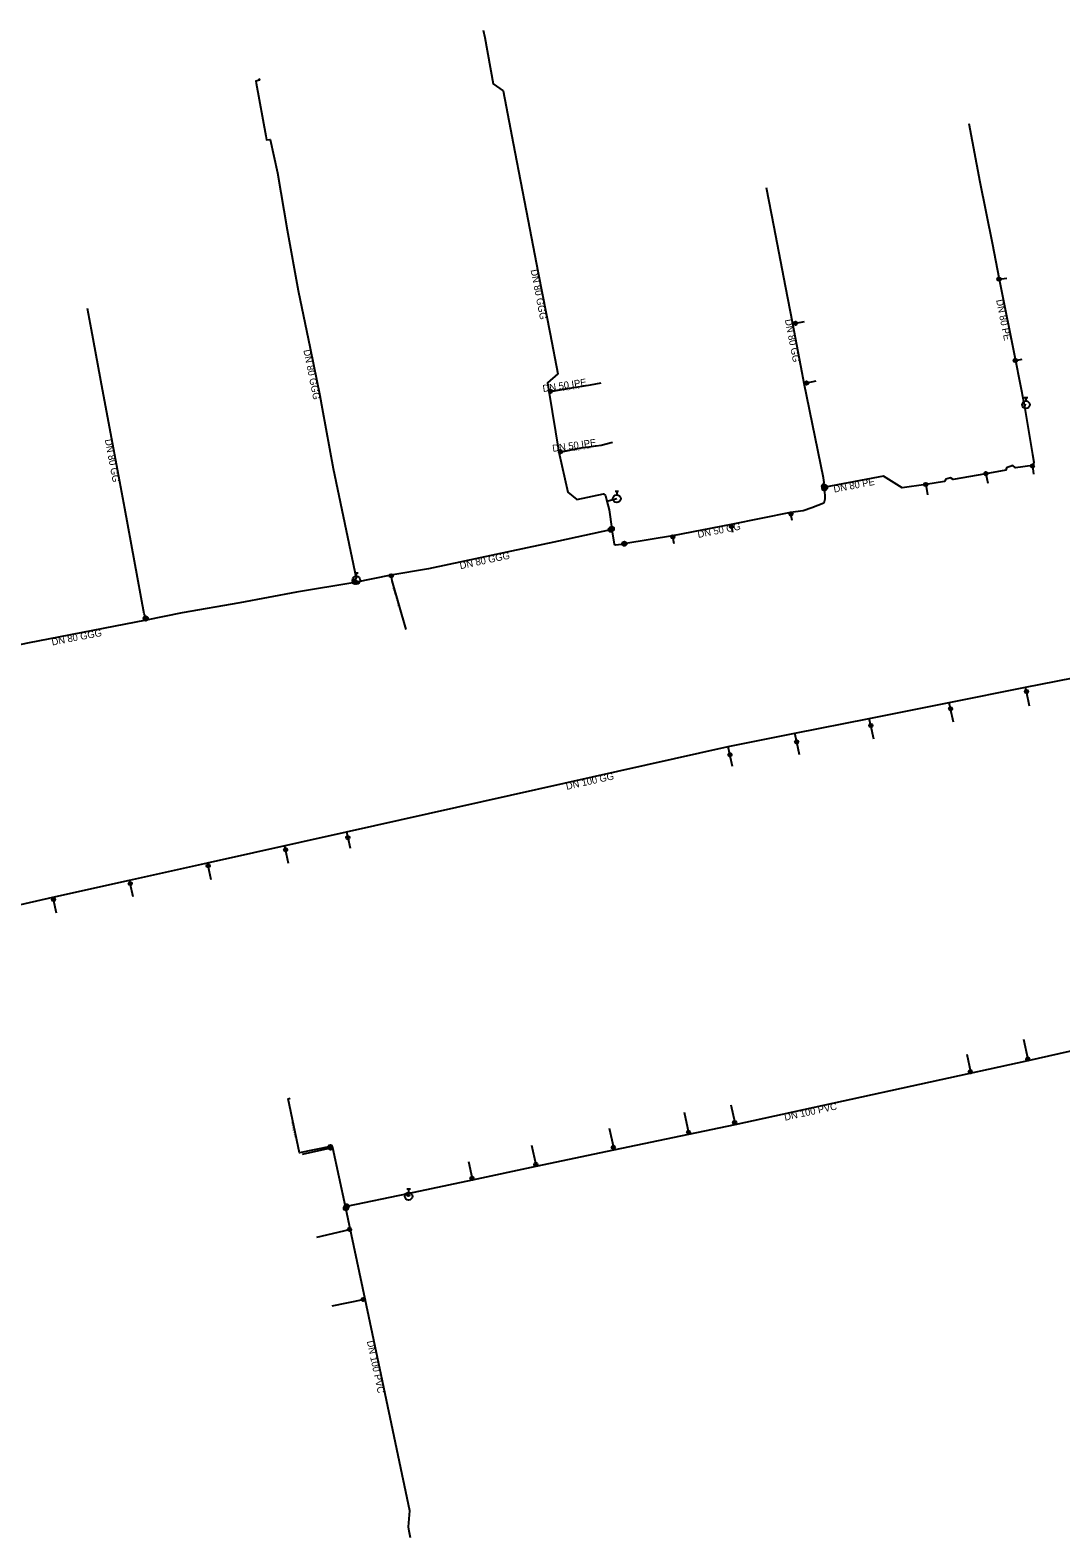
# Model space of a CAD drawing. Extents: x -452548 to -451108, y -1100145 to -1099658.
# Drawn here: x -452307.3 to -452071.3, y -1100124.5 to -1099779.2 of the extents above; entities that cross this region are included whole.
import ezdxf

# ---------------------------------------------------------------- set-up
doc = ezdxf.new("R2010")
doc.units = 0
for name, color, linetype in [('_hydrantova_odbocka_', 7, 'Continuous'), ('_pripojka_prevzato_z_dokumentace_', 7, 'Continuous'), ('_pripojka_priblizne_', 7, 'Continuous'), ('_voda_smvak_prevzato_z_dokumentace_', 7, 'Continuous'), ('_vodovodni_chranicka_', 7, 'Continuous'), ('Default', 7, 'Continuous'), ('MoLevel 27', 7, 'Continuous'), ('MoLevel 28', 7, 'Continuous'), ('MoLevel 32', 7, 'Continuous'), ('MoLevel 46', 7, 'Continuous'), ('MoLevel 53', 7, 'Continuous'), ('MoLevel 55', 7, 'Continuous'), ('MoLevel 60', 7, 'Continuous')]:
    doc.layers.add(name, color=color, linetype=linetype)

# ---------------------------------------------------------------- blocks, each defined once
blk = doc.blocks.new('_uzaver_')
at = {"layer": 'Default'}
for p, q in [((-0.000035, -0.000035), (0.000035, 0.000035)), ((0.000035, -0.000035), (-0.000035, 0.000035))]:
    blk.add_line(p, q, dxfattribs=at)
for radius in [0.00005, 0.0000025]:
    blk.add_circle((0, 0), radius, dxfattribs=at)
blk = doc.blocks.new('_uzaver_pripojka_')
at = {"layer": 'Default'}
for p, q in [((-0.000035, -0.000035), (0.000035, 0.000035)), ((0.000035, -0.000035), (-0.000035, 0.000035))]:
    blk.add_line(p, q, dxfattribs=at)
for radius in [0.00005, 0.0000025]:
    blk.add_circle((0, 0), radius, dxfattribs=at)
blk = doc.blocks.new('_hydrant_voda_')
at = {"layer": 'Default'}
for p, q in [((-0.000023, 0.000095), (0.000023, 0.000095)), ((0, 0.000095), (0, 0.00005))]:
    blk.add_line(p, q, dxfattribs=at)
blk.add_circle((0, 0), 0.00005, dxfattribs=at)

msp = doc.modelspace()

# ---------------------------------------------------------------- linework, layer by layer
at = {"layer": '_hydrantova_odbocka_'}
for p, q in [((-452079.72, -1099864.93), (-452079.34, -1099864.99)), ((-452175.26, -1099887.05), (-452173.01, -1099886.49)), ((-452233.09, -1099905.3), (-452232.66, -1099905.17))]:
    msp.add_line(p, q, dxfattribs=at)
msp.add_lwpolyline([(-452220.84, -1100045.6), (-452220.75, -1100045.96), (-452220.69, -1100046.26)], dxfattribs=at)
at = {"layer": '_pripojka_prevzato_z_dokumentace_'}
for p, q in [((-452085.49, -1099836.21), (-452083.74, -1099835.99)), ((-452081.76, -1099854.85), (-452080.17, -1099854.54)), ((-452088.49, -1099880.77), (-452088.04, -1099882.91)), ((-452102.28, -1099883.25), (-452101.9, -1099885.59)), ((-452224.55, -1099905.29), (-452221.31, -1099916.46))]:
    msp.add_line(p, q, dxfattribs=at)
for points in [[(-452130.13, -1099845.96), (-452132.13, -1099846.34), (-452132.72, -1099846.46)], [(-452188.55, -1099861.88), (-452188.18, -1099861.91), (-452183.85, -1099861.16), (-452179.05, -1099860.42), (-452176.58, -1099859.94)], [(-452127.48, -1099859.62), (-452129.59, -1099860.02), (-452130.09, -1099860.12)], [(-452186.29, -1099875.81), (-452185.9, -1099875.74), (-452181.2, -1099874.88), (-452176.63, -1099874.23), (-452173.99, -1099873.54)], [(-452077.87, -1099878.9), (-452077.85, -1099879), (-452077.63, -1099880.92)], [(-452132.85, -1099891.5), (-452133.13, -1099890.02), (-452133.21, -1099889.67)], [(-452146.84, -1099892.38), (-452146.75, -1099892.84), (-452146.49, -1099894.18)], [(-452159.88, -1099896.82), (-452160.19, -1099895.25), (-452160.23, -1099895.03)], [(-452224.72, -1099904.04), (-452224.67, -1099904.15), (-452224.55, -1099905.29)], [(-452078.51, -1099934), (-452079.21, -1099930.67), (-452079.42, -1099929.69)], [(-452095.94, -1099937.7), (-452096.59, -1099934.61), (-452096.89, -1099933.18)], [(-452114.19, -1099941.58), (-452114.85, -1099938.45), (-452115.2, -1099936.84)], [(-452131.2, -1099945.19), (-452131.83, -1099942.24), (-452132.25, -1099940.24)], [(-452146.52, -1099947.8), (-452147.1, -1099945.11), (-452147.49, -1099943.29)], [(-452234.9, -1099962.8), (-452234.6, -1099964.13), (-452234.07, -1099966.53)], [(-452248.17, -1099970.03), (-452248.84, -1099966.88), (-452249.05, -1099965.95)], [(-452265.89, -1099973.83), (-452266.59, -1099970.56), (-452266.73, -1099969.9)], [(-452283.78, -1099977.67), (-452284.42, -1099974.65), (-452284.59, -1099973.89)], [(-452301.34, -1099981.43), (-452302, -1099978.31), (-452302.11, -1099977.8)], [(-452079.89, -1100010.26), (-452078.92, -1100014.83), (-452078.82, -1100015.2)], [(-452092.9, -1100013.73), (-452092.05, -1100017.72), (-452091.97, -1100018.09)], [(-452157.59, -1100026.97), (-452156.58, -1100031.63), (-452156.49, -1100032.04)], [(-452146.93, -1100025.3), (-452146.02, -1100029.36), (-452145.92, -1100029.82)], [(-452174.75, -1100030.7), (-452173.79, -1100035.05), (-452173.67, -1100035.66)], [(-452192.53, -1100034.53), (-452191.56, -1100038.96), (-452191.46, -1100039.41)], [(-452238.06, -1100035.16), (-452238.54, -1100035.26), (-452245.07, -1100036.68)], [(-452206.99, -1100038.31), (-452206.16, -1100042.16), (-452206.09, -1100042.49)], [(-452241.67, -1100055.6), (-452234.22, -1100053.84), (-452234.03, -1100053.81)], [(-452238.22, -1100071.38), (-452231.05, -1100069.89), (-452230.66, -1100069.8)]]:
    msp.add_lwpolyline(points, dxfattribs=at)
at = {"layer": '_pripojka_priblizne_'}
msp.add_lwpolyline([(-452238.11, -1100034.93), (-452238.6, -1100034.86), (-452245.65, -1100036.31), (-452248.28, -1100023.95), (-452247.8, -1100023.81)], dxfattribs=at)
at = {"layer": '_voda_smvak_prevzato_z_dokumentace_'}
for p, q in [((-452125.49, -1099883.88), (-452125.55, -1099883.68)), ((-452125.31, -1099883.88), (-452125.49, -1099883.88)), ((-452125.49, -1099883.88), (-452125.49, -1099884.15)), ((-452128.36, -1099888.61), (-452130.37, -1099889.32)), ((-452174.12, -1099893.6), (-452174.43, -1099893.62)), ((-452171.28, -1099896.81), (-452170.98, -1099896.75)), ((-452233.01, -1099905.71), (-452233.01, -1099905.54)), ((-452280.76, -1099914.36), (-452280.88, -1099913.94)), ((-452235.13, -1100048.61), (-452234.84, -1100048.55)), ((-452235.05, -1100049.01), (-452235.13, -1100048.61))]:
    msp.add_line(p, q, dxfattribs=at)
for points in [[(-452203.58, -1099779.19), (-452203.22, -1099780.9), (-452201.34, -1099791.49), (-452199.04, -1099793.11), (-452196.35, -1099807.03), (-452193.76, -1099820.48), (-452191, -1099834.78), (-452188.3, -1099848.74), (-452186.54, -1099857.9), (-452188.9, -1099859.94), (-452188.55, -1099861.88), (-452186.29, -1099875.81), (-452184.23, -1099885.03), (-452182.18, -1099886.71), (-452176.09, -1099885.37), (-452175.58, -1099885.78), (-452175.26, -1099887.05), (-452174.76, -1099889.05), (-452174.16, -1099893.41)], [(-452254.94, -1099790.28), (-452254.84, -1099790.62), (-452255.66, -1099790.85), (-452255.56, -1099791.37), (-452253.39, -1099803.36), (-452253.21, -1099804.34), (-452252.37, -1099804.21), (-452250.74, -1099811.9), (-452248.48, -1099824.93), (-452245.97, -1099838.83), (-452243.25, -1099851.99), (-452241.04, -1099862.89), (-452240.49, -1099865.82), (-452237.94, -1099879.57), (-452232.72, -1099904.67), (-452233.16, -1099905)], [(-452092.44, -1099800.57), (-452089.86, -1099813.92), (-452087.08, -1099827.88), (-452085.49, -1099836.21), (-452081.76, -1099854.85), (-452079.72, -1099864.93), (-452077.8, -1099876.38)], [(-452130.56, -1099857.67), (-452132.72, -1099846.46), (-452134.37, -1099837.86), (-452136.98, -1099824.35), (-452138.71, -1099815.34)], [(-452281.25, -1099912.84), (-452285.66, -1099888.75), (-452288.18, -1099875.32), (-452290.76, -1099861.51), (-452293.32, -1099847.86), (-452294.24, -1099842.92)], [(-452125.71, -1099881.72), (-452130.09, -1099860.12), (-452130.56, -1099857.67)], [(-452077.8, -1099876.38), (-452077.5, -1099878.16), (-452077.65, -1099878.87), (-452077.87, -1099878.9), (-452081.69, -1099879.4), (-452082.3, -1099878.92), (-452083.75, -1099879.45), (-452083.96, -1099879.98), (-452088.49, -1099880.77), (-452096, -1099882.14), (-452096.61, -1099881.73), (-452097.67, -1099882.03), (-452097.97, -1099882.54), (-452102.28, -1099883.25), (-452107.71, -1099884.02), (-452111.95, -1099881.32), (-452125.31, -1099883.88)], [(-452125.55, -1099883.68), (-452125.65, -1099883.14), (-452125.53, -1099882.76), (-452125.71, -1099881.72)], [(-452125.49, -1099884.15), (-452125.39, -1099886.63), (-452125.59, -1099887.53), (-452128.36, -1099888.61)], [(-452130.37, -1099889.32), (-452133.21, -1099889.67), (-452146.84, -1099892.38), (-452160.23, -1099895.03), (-452170.98, -1099896.75)], [(-452174.43, -1099893.62), (-452186.34, -1099896.21), (-452216.14, -1099902.57), (-452224.72, -1099904.04), (-452233.01, -1099905.71), (-452246.32, -1099907.88), (-452259.32, -1099910.32), (-452272.52, -1099912.61), (-452280.76, -1099914.36)], [(-452174.16, -1099893.41), (-452174.12, -1099893.6), (-452173.62, -1099896.88), (-452173.28, -1099897.1), (-452171.28, -1099896.81)], [(-452233.01, -1099905.54), (-452233.09, -1099905.3), (-452233.16, -1099905)], [(-452280.88, -1099913.94), (-452280.99, -1099913.58), (-452281.11, -1099913.21), (-452281.25, -1099912.84)], [(-452280.76, -1099914.36), (-452307.91, -1099919.59), (-452321.54, -1099922.48), (-452327.65, -1099923.56)], [(-452346.93, -1099987.86), (-452316.58, -1099981.03), (-452302.11, -1099977.8), (-452284.59, -1099973.89), (-452266.73, -1099969.9), (-452234.9, -1099962.8), (-452147.49, -1099943.29), (-452132.25, -1099940.24), (-452115.2, -1099936.84), (-452096.89, -1099933.18), (-452079.42, -1099929.69), (-452064.98, -1099926.81), (-452051.17, -1099924.05), (-452046.02, -1099949.05), (-452030.12, -1099945.84), (-452027.65, -1099944.96)], [(-452234.84, -1100048.55), (-452220.84, -1100045.6), (-452206.09, -1100042.49), (-452191.46, -1100039.41), (-452173.67, -1100035.66), (-452156.49, -1100032.04), (-452145.92, -1100029.82), (-452078.82, -1100015.2), (-452061.54, -1100011.25), (-452043.24, -1100007.07), (-452027.74, -1100003.53), (-452019.95, -1100002.05)], [(-452235.13, -1100048.61), (-452238.06, -1100035.16), (-452238.11, -1100034.93)], [(-452220.23, -1100124.5), (-452220.54, -1100122.98), (-452220.71, -1100121.99), (-452220.43, -1100118.28), (-452226.69, -1100088.59), (-452230.66, -1100069.8), (-452235.05, -1100049.01)]]:
    msp.add_lwpolyline(points, dxfattribs=at)
at = {"layer": '_vodovodni_chranicka_'}
for points in [[(-452187.76, -1099861.84), (-452183.85, -1099861.16), (-452179.05, -1099860.42)], [(-452185.71, -1099875.74), (-452181.2, -1099874.88), (-452176.63, -1099874.23)]]:
    msp.add_lwpolyline(points, dxfattribs=at)

# ---------------------------------------------------------------- block references
at = {"layer": 'MoLevel 27'}
for p, xscale, yscale in [((-452125.55, -1099883.68), 10000, 10000), ((-452125.49, -1099884.16), 10000, 10000), ((-452125.31, -1099883.88), 10000, 10000), ((-452220.75, -1100045.96), 5000, 5000)]:
    msp.add_blockref('_uzaver_', p, dxfattribs=dict(at, xscale=xscale, yscale=yscale))
for p, xscale, yscale, rotation in [((-452174.43, -1099893.62), 9999.999999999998, 10000, 9.04000680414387), ((-452174.16, -1099893.41), 10000, 9999.999999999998, -79.92900643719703), ((-452171.28, -1099896.81), 10000, 9999.999999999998, 9.15357245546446), ((-452233.01, -1099905.54), 9999.999999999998, 10000, -79.33021719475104), ((-452280.88, -1099913.94), 10000.000000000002, 9999.999999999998, -78.33640344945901), ((-452235.05, -1100049.01), 10000.000000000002, 9999.999999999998, -78.10182262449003), ((-452234.84, -1100048.55), 9999.999999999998, 10000, 11.896829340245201)]:
    msp.add_blockref('_uzaver_', p, dxfattribs=dict(at, xscale=xscale, yscale=yscale, rotation=rotation))
at = {"layer": 'MoLevel 28', "xscale": 17636.68430335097, "yscale": 17636.68430335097}
for p in [(-452079.34, -1099864.99), (-452173.01, -1099886.49), (-452232.66, -1099905.17), (-452220.69, -1100046.26)]:
    msp.add_blockref('_hydrant_voda_', p, dxfattribs=at)
at = {"layer": 'MoLevel 53', "xscale": 7999.999999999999, "yscale": 7999.999999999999}
for p in [(-452085.49, -1099836.21), (-452132.13, -1099846.34), (-452081.77, -1099854.85), (-452188.18, -1099861.91), (-452129.57, -1099860.02), (-452185.9, -1099875.74), (-452077.85, -1099879), (-452102.28, -1099883.25), (-452088.49, -1099880.77), (-452133.13, -1099890.02), (-452146.75, -1099892.84), (-452160.19, -1099895.25), (-452224.67, -1099904.15), (-452079.21, -1099930.67), (-452096.59, -1099934.61), (-452114.85, -1099938.45), (-452147.1, -1099945.11), (-452131.83, -1099942.24), (-452234.6, -1099964.13), (-452248.84, -1099966.88), (-452266.59, -1099970.56), (-452284.42, -1099974.65), (-452302, -1099978.31), (-452092.05, -1100017.72), (-452078.92, -1100014.83), (-452156.58, -1100031.63), (-452146.02, -1100029.36), (-452238.6, -1100034.86), (-452238.54, -1100035.26), (-452173.79, -1100035.05), (-452206.16, -1100042.16), (-452191.56, -1100038.96), (-452234.22, -1100053.84), (-452231.05, -1100069.89)]:
    msp.add_blockref('_uzaver_pripojka_', p, dxfattribs=at)

# ---------------------------------------------------------------- texts
at = {"layer": 'MoLevel 32'}
msp.add_text('DN 100 PVC', height=0.455, rotation=282.0357, dxfattribs=at).set_placement((-452247.61, -1100029.28))
at = {"layer": 'MoLevel 46'}
for s, rotation, p in [('DN 80 GGG', 280.9362, (-452192.76, -1099834.14)), ('DN 80 PE', 281.3028, (-452086.17, -1099841.02)), ('DN 80 GG', 280.9009, (-452134.53, -1099845.53)), ('DN 80 GGG', 281.4385, (-452244.78, -1099852.5)), ('DN 80 GG', 280.5988, (-452290.24, -1099873)), ('DN 80 PE', 10.8275, (-452123.23, -1099885.12)), ('DN 50 GG', 11.2309, (-452154.36, -1099895.5)), ('DN 80 GGG', 12.0479, (-452208.81, -1099902.65)), ('DN 80 GGG', 10.9117, (-452302.27, -1099920.14)), ('DN 100 GG', 12.5824, (-452184.48, -1099953.19)), ('DN 100 PVC', 12.2868, (-452134.49, -1100028.97)), ('DN 100 PVC', 281.9191, (-452230.25, -1100079.49))]:
    msp.add_text(s, height=1.605, rotation=rotation, dxfattribs=at).set_placement(p)
at = {"layer": 'MoLevel 55'}
for s, rotation, p in [("DN 25 - 1'' PE", 8.7246, (-452185.39, -1099861.85)), ("DN 25 - 1'' PE", 8.044, (-452182.97, -1099875.59)), ("DN 20 - 3/4'' PE", 286.1794, (-452224.37, -1099906.95))]:
    msp.add_text(s, height=0.455, rotation=rotation, dxfattribs=at).set_placement(p)
at = {"layer": 'MoLevel 60'}
for rotation, p in [(8.7246, (-452189.87, -1099862.08)), (8.044, (-452187.66, -1099875.79))]:
    msp.add_text('DN 50 IPE', height=1.605, rotation=rotation, dxfattribs=at).set_placement(p)

doc.saveas('drawing.dxf')
